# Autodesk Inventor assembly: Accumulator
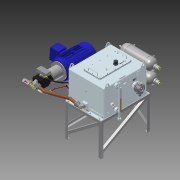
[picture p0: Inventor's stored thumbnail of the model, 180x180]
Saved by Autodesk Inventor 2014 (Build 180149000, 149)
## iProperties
Created: 2002-07
Part Number: Accumulator
Description: POWER PACK ASSY
Document SubType Name: Assembly
Designer: Autodesk, Inc.
Mass: 801000 g
Surface Area: 191391 cm^2
Volume: 112018 cm^3
Density: 7.15062 g/cm^3
Company: Autodesk, Inc.
_PSKETCH_MXID: 114
Control State: 0
Master: False
Checked Out: True
Shininess: 20.0
Length Units: 11272
Angle Units: 11279
Time Units: 11290
Mass Units: 11286
Length Display Precision: 3
Angle Display Precision: 2
Density: 0.0
Volumn: 0.0
Area: 0.0
PropertySet Name: Model Information
Title: Accumulator
Author: Autodesk, Inc.
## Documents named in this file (67)
- C:\Users\iTools\Desktop\tutorial files\Tube and Pipe\Accumulator\Accumulator.iam
- C:\Users\iTools\Desktop\tutorial files\Tube and Pipe\Accumulator\Parts\51361.ipt
- C:\Users\iTools\Desktop\tutorial files\Tube and Pipe\Accumulator\Parts\207905.ipt
- C:\Users\iTools\Desktop\tutorial files\Tube and Pipe\Accumulator\Parts\204389.ipt
- C:\Users\iTools\Desktop\tutorial files\Tube and Pipe\Accumulator\Parts\46959.ipt
- C:\Users\iTools\Desktop\tutorial files\Tube and Pipe\Accumulator\Parts\37454.ipt
- C:\Users\iTools\Desktop\tutorial files\Tube and Pipe\Accumulator\Parts\47290.ipt
- C:\Users\iTools\Desktop\tutorial files\Tube and Pipe\Accumulator\Parts\235517.ipt
- C:\Users\iTools\Desktop\tutorial files\Tube and Pipe\Accumulator\Parts\237648.ipt
- C:\Users\iTools\Desktop\tutorial files\Tube and Pipe\Accumulator\Parts\232894.ipt
- C:\Users\iTools\Desktop\tutorial files\Tube and Pipe\Accumulator\Parts\11587.ipt
- C:\Users\iTools\Desktop\tutorial files\Tube and Pipe\Accumulator\Parts\238807.ipt
- C:\Users\iTools\Desktop\tutorial files\Tube and Pipe\Accumulator\Parts\19754.ipt
- C:\Users\iTools\Desktop\tutorial files\Tube and Pipe\Accumulator\Parts\230976.ipt
- C:\Users\iTools\Desktop\tutorial files\Tube and Pipe\Accumulator\Parts\228458.ipt
- C:\Users\iTools\Desktop\tutorial files\Tube and Pipe\Accumulator\Parts\231851.ipt
- C:\Users\iTools\Desktop\tutorial files\Tube and Pipe\Accumulator\Parts\229672.ipt
- C:\Users\iTools\Desktop\tutorial files\Tube and Pipe\Accumulator\Parts\245671.ipt
- C:\Users\iTools\Desktop\tutorial files\Tube and Pipe\Accumulator\Parts\245667.ipt
- C:\Users\iTools\Desktop\tutorial files\Tube and Pipe\Accumulator\Parts\243992.ipt
- C:\Users\iTools\Desktop\tutorial files\Tube and Pipe\Accumulator\Parts\247502.ipt
- C:\Users\iTools\Desktop\tutorial files\Tube and Pipe\Accumulator\Parts\244752.ipt
- C:\Users\iTools\Desktop\tutorial files\Tube and Pipe\Accumulator\Parts\245748.ipt
- C:\Users\iTools\Desktop\tutorial files\Tube and Pipe\Accumulator\Parts\233841.ipt
- C:\Users\iTools\Desktop\tutorial files\Tube and Pipe\Accumulator\Parts\237738.ipt
- C:\Users\iTools\Desktop\tutorial files\Tube and Pipe\Accumulator\Parts\248216.ipt
- C:\Users\iTools\Desktop\tutorial files\Tube and Pipe\Accumulator\Parts\209140.ipt
- C:\Users\iTools\Desktop\tutorial files\Tube and Pipe\Accumulator\Parts\51573.ipt
- C:\Users\iTools\Desktop\tutorial files\Tube and Pipe\Accumulator\Parts\244403.ipt
- C:\Users\iTools\Desktop\tutorial files\Tube and Pipe\Accumulator\Parts\248780.ipt
- C:\Users\iTools\Desktop\tutorial files\Tube and Pipe\Accumulator\Parts\247846.ipt
- C:\Users\iTools\Desktop\tutorial files\Tube and Pipe\Accumulator\Parts\238527.ipt
- C:\Users\iTools\Desktop\tutorial files\Tube and Pipe\Accumulator\Parts\240811.ipt
- C:\Users\iTools\Desktop\tutorial files\Tube and Pipe\Accumulator\Parts\51442.iam
- C:\Users\iTools\Desktop\tutorial files\Tube and Pipe\Accumulator\Parts\248801.ipt
- C:\Users\iTools\Desktop\tutorial files\Tube and Pipe\Accumulator\Parts\46412.ipt
- C:\Users\iTools\Desktop\tutorial files\Tube and Pipe\Accumulator\Parts\HF32746.ipt
- C:\Users\iTools\Desktop\tutorial files\Tube and Pipe\Accumulator\Parts\R13811195.ipt
- C:\Users\iTools\Desktop\tutorial files\Tube and Pipe\Accumulator\Parts\220667.ipt
- C:\Users\iTools\Desktop\tutorial files\Tube and Pipe\Accumulator\Parts\557202.ipt
- C:\Users\iTools\Desktop\tutorial files\Tube and Pipe\Accumulator\Parts\558560.ipt
- C:\Users\iTools\Desktop\tutorial files\Tube and Pipe\Accumulator\Parts\248809.ipt
- C:\Users\iTools\Desktop\tutorial files\Tube and Pipe\Accumulator\Parts\237737n.ipt
- C:\Users\iTools\Desktop\tutorial files\Tube and Pipe\Accumulator\Parts\237739n.ipt
- C:\Users\iTools\Desktop\tutorial files\Tube and Pipe\Accumulator\Parts\HF33269.ipt
- C:\Users\iTools\Desktop\tutorial files\Tube and Pipe\Accumulator\Parts\HF32747.ipt
- C:\Users\iTools\Desktop\tutorial files\Tube and Pipe\Accumulator\AIP\piping runs.1067628895400.iam
- C:\Users\iTools\Desktop\tutorial files\Tube and Pipe\Accumulator\Parts\Mount Frame.iam
- C:\Users\iTools\Desktop\tutorial files\Tube and Pipe\Accumulator\Standard Parts\ANSI B18.2.1 - 5_8-11 UNC - 1.5(3).ipt
- C:\Users\iTools\Desktop\tutorial files\Tube and Pipe\Accumulator\Standard Parts\ANSI B18.2.1 - 3_8-16 UNC - 1(3).ipt
- C:\Users\iTools\Desktop\tutorial files\Tube and Pipe\Accumulator\Standard Parts\ANSI B18.2.1 - 5_8-11 UNC - 2.25(3).ipt
- C:\Users\iTools\Desktop\tutorial files\Tube and Pipe\Accumulator\Standard Parts\ANSI B18.2.1 - 1_2-13 UNC - 1(3).ipt
- C:\Users\iTools\Desktop\tutorial files\Tube and Pipe\Accumulator\Standard Parts\ANSI B18.2.1 - 1_2-13 UNC - 1.75(3).ipt
- C:\Users\iTools\Desktop\tutorial files\Tube and Pipe\Accumulator\Standard Parts\ANSI B18.2.1 - 3_8-16 UNC - 0.75(3).ipt
- C:\Program Files\Autodesk\Inventor 2010\Tutorial Files\Tube & Pipe\Accumulator\Parts\MC-B.ipt
- C:\Program Files\Autodesk\Inventor 2010\Tutorial Files\Tube & Pipe\Accumulator\Parts\MC-G.ipt
- C:\Program Files\Autodesk\Inventor 2010\Tutorial Files\Tube & Pipe\Accumulator\Parts\EL-BC9.ipt
- C:\Program Files\Autodesk\Inventor 2010\Tutorial Files\Tube & Pipe\Accumulator\Parts\C9C9G-C9GC9.ipt
- C:\Program Files\Autodesk\Inventor 2010\Tutorial Files\Tube & Pipe\Accumulator\Parts\EL-C9G.ipt
- C:\Program Files\Autodesk\Inventor 2010\Tutorial Files\Tube & Pipe\Accumulator\Parts\ST-A9G.ipt
- C:\Program Files\Autodesk\Inventor 2010\Tutorial Files\Tube & Pipe\Accumulator\Parts\STATO.ipt
- C:\Program Files\Autodesk\Inventor 2010\Tutorial Files\Tube & Pipe\Accumulator\Parts\Lock-nut.ipt
- C:\Program Files\Autodesk\Inventor 2010\Tutorial Files\Tube & Pipe\Accumulator\Parts\ST-BQ.ipt
- C:\Program Files\Autodesk\Inventor 2010\Tutorial Files\Tube & Pipe\Accumulator\Parts\ST-GG.ipt
- C:\Program Files\Autodesk\Inventor 2010\Tutorial Files\Tube & Pipe\Accumulator\Parts\C9C9C9_C9C9A9_C9A9C9.ipt
- C:\Program Files\Autodesk\Inventor 2010\Tutorial Files\Tube & Pipe\Accumulator\Parts\ST-BC9.ipt
- C:\Program Files\Autodesk\Inventor 2010\Tutorial Files\Tube & Pipe\Accumulator\Parts\Threaded Weld Stud.ipt
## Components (138 placed, 53 different names)
1. Tube & Pipe Runs [sub-assembly]
2. 51361:1 — Mate:1, Mate:2, Mate:3, Mate:4, Mate:5, Mate:6, Mate:7, Mate:8, Mate:9, Mate:10, Mate:11, Mate:12, Mate:21, Mate:22, Mate:23, Mate:25, Mate:30, Mate:33, Mate:40, Mate:41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
3. 51442:1 [sub-assembly] — Mate:55, Mate:56, Angle:3, Mate:105, Mate:106, Angle:5, Mate:172, Mate:173
4. 244752:2 — Mate:120, Flush:3, Angle:6, Mate:121, Mate:122, Mate:158
5. 244752:1 — Mate:118, Mate:119, Flush:3, Angle:7, Mate:123, Mate:124, Mate:159
6. 207905:1 — Mate:1, Mate:7, Mate:8, Mate:14, Mate:18, Mate:120
7. 207905:2 — Mate:2, Mate:5, Mate:6, Mate:13, Mate:17, Mate:63, Mate:64, Mate:118, Mate:119
8. 207905:3 — Mate:4, Mate:11, Mate:12, Mate:15, Mate:19
9. 207905:4 — Mate:3, Mate:9, Mate:10, Mate:16, Mate:20
10. 46959:1 — Mate:13, Mate:17
11. 46959:2 — Mate:14, Mate:18
12. 46959:3 — Mate:16, Mate:20
13. 46959:4 — Mate:15, Mate:19
14. 47290:1 — Mate:24, Mate:25, Mate:26, Mate:27, Mate:28, Mate:29, Mate:38, Mate:39, Mate:59, Mate:60, Mate:97, Mate:98, Mate:99
15. 37454:1 — Mate:21, Mate:22, Mate:23, Mate:24, Mate:26
16. 235517:1 — Mate:27, Mate:28, Mate:29
17. 237648:1 — Mate:30, Mate:115, Mate:116, Mate:125, Mate:126, Mate:128, Mate:129
18. 11587:1 — Mate:31, Mate:32, Mate:33, Mate:94, Mate:95
19. 245671:1 — Mate:42, Mate:43, Mate:44, Mate:45
20. 245667:1 — Mate:44, Mate:45, Angle:1
21. 243992:1 — Mate:57, Mate:58, Mate:107
22. 248801:1 — Mate:52, Mate:53, Mate:54
23. 245748:1 — Mate:48, Mate:51, Mate:52
24. 245748:2 — Mate:49, Mate:50
25. 230976:1 — Mate:38, Mate:39
26. 229672:1 — Mate:40, Mate:41
27. 238807:1 — Mate:46, Mate:47, Angle:2, Mate:164, Mate:165
28. 248809:1 — Mate:105, Mate:106, Angle:5, Mate:107, Mate:108, Mate:113, Mate:114, Angle:8
29. 237738:1 — Mate:55, Mate:56, Angle:3, Flush:6, Mate:163
30. 248780:1 — Mate:57, Mate:58, Mate:108
31. 209140:2 — Mate:123, Mate:124, Mate:156
32. 209140:3 — Mate:121, Mate:122, Mate:157
33. 220667:1 — Mate:94, Mate:95, Mate:96
34. 557202:1 — Mate:97, Mate:98, Mate:99
35. 558560:1 — Mate:100, Mate:101, Mate:102
36. 248780:2 — Mate:113, Mate:114, Mate:134, Mate:135
37. 19754:1 — Mate:115, Mate:116
38. 233841:1 — Mate:128, Mate:129
39. 237737n:1
40. 248216:1 — Mate:138, Mate:139, Angle:9, Mate:140, Mate:141
41. 51573:1 — Mate:134, Mate:135, Angle:8, Mate:136, Mate:137, Angle:9
42. 244403:1 — Mate:136, Mate:137, Mate:138, Mate:139
43. 247846:1 — Mate:140, Mate:141
44. 237739n:1 — Mate:166, Mate:167
45. 238527:1 — Mate:146, Mate:147, Angle:10, Mate:161, Mate:162
46. 247502:1 — Mate:144, Mate:145, Mate:146, Mate:147
47. 240811:1 — Mate:156, Mate:159
48. 240811:2 — Mate:157, Mate:158
49. 46412:1 — Mate:160
50. HF32746:1 — Flush:6, Mate:163
51. HF32746:2 — Mate:161, Mate:162
52. HF32746:3 — Mate:164, Mate:165
53. HF32746:4 — Mate:166, Mate:167
54. HF33269:1 — Flush:7, Mate:168, Mate:169, Mate:170, Mate:171
55. HF32747:1 — Mate:170, Mate:171
56. HF33269:2 — Mate:172, Mate:173, Mate:174, Mate:175, Mate:176
57. HF32747:2 — Mate:175, Mate:176
58. Mount Frame:1 [sub-assembly] — Flush:8, Flush:9
59. 232894:1 — Mate:31, Mate:32
60. 232894:2
61. 232894:3
62. 232894:4
63. Hex Cap Screw - Inch 3/8-16 UNC - 0.75:1
64. 204389:1 — Mate:59, Mate:60
65. Hex Cap Screw - Inch 3/8-16 UNC - 0.75:2
66. 204389:2
67. Hex Cap Screw - Inch 3/8-16 UNC - 0.75:3
68. 204389:3
69. Hex Cap Screw - Inch 3/8-16 UNC - 0.75:4
70. 204389:4
71. Hex Cap Screw - Inch 3/8-16 UNC - 0.75:5
72. 204389:6
73. Hex Cap Screw - Inch 3/8-16 UNC - 0.75:6
74. 204389:7
75. Hex Cap Screw - Inch 3/8-16 UNC - 0.75:7
76. 204389:9
77. Hex Cap Screw - Inch 3/8-16 UNC - 0.75:8
78. 204389:10
79. Hex Cap Screw - Inch 3/8-16 UNC - 0.75:9
80. 204389:12
81. Hex Cap Screw - Inch 3/8-16 UNC - 0.75:10
82. 204389:13
83. Hex Cap Screw - Inch 3/8-16 UNC - 0.75:11
84. 204389:14
85. Hex Cap Screw - Inch 3/8-16 UNC - 0.75:12
86. 204389:15
87. Hex Cap Screw - Inch 3/8-16 UNC - 1:1
88. 231851:1 — Mate:64, Mate:66
89. Hex Cap Screw - Inch 3/8-16 UNC - 1:5
90. 231851:2 — Mate:63, Mate:65
91. Hex Cap Screw - Inch 3/8-16 UNC - 1:2
92. 231851:3
93. Hex Cap Screw - Inch 3/8-16 UNC - 1:6
94. 231851:4
95. Hex Cap Screw - Inch 3/8-16 UNC - 1:3
96. 231851:5
97. Hex Cap Screw - Inch 3/8-16 UNC - 1:7
98. 231851:6
99. Hex Cap Screw - Inch 3/8-16 UNC - 1:4
100. 231851:7
101. Hex Cap Screw - Inch 3/8-16 UNC - 1:8
102. 231851:8
103. Hex Cap Screw - Inch 1/2-13 UNC - 1.75:1
104. Hex Cap Screw - Inch 1/2-13 UNC - 1.75:2
105. Hex Cap Screw - Inch 1/2-13 UNC - 1.75:3
106. Hex Cap Screw - Inch 1/2-13 UNC - 1.75:4
107. Hex Cap Screw - Inch 1/2-13 UNC - 1:1
108. Hex Cap Screw - Inch 1/2-13 UNC - 1:3
109. Hex Cap Screw - Inch 1/2-13 UNC - 1:5
110. Hex Cap Screw - Inch 1/2-13 UNC - 1:7
111. Hex Cap Screw - Inch 1/2-13 UNC - 1:2
112. Hex Cap Screw - Inch 1/2-13 UNC - 1:4
113. Hex Cap Screw - Inch 1/2-13 UNC - 1:6
114. Hex Cap Screw - Inch 1/2-13 UNC - 1:8
115. Hex Cap Screw - Inch 5/8-11 UNC - 1.5:1
116. 228458:1 — Mate:85
117. Hex Cap Screw - Inch 5/8-11 UNC - 1.5:5
118. 228458:5 — Mate:89
119. Hex Cap Screw - Inch 5/8-11 UNC - 1.5:2
120. 228458:2
121. Hex Cap Screw - Inch 5/8-11 UNC - 1.5:6
122. 228458:6
123. Hex Cap Screw - Inch 5/8-11 UNC - 1.5:3
124. 228458:3
125. Hex Cap Screw - Inch 5/8-11 UNC - 1.5:7
126. 228458:7
127. Hex Cap Screw - Inch 5/8-11 UNC - 1.5:4
128. 228458:4
129. Hex Cap Screw - Inch 5/8-11 UNC - 1.5:8
130. 228458:8
131. R13811195:9
132. Hex Cap Screw - Inch 5/8-11 UNC - 2.25:1
133. R13811195:16
134. Hex Cap Screw - Inch 5/8-11 UNC - 2.25:2
135. R13811195:17
136. Hex Cap Screw - Inch 5/8-11 UNC - 2.25:3
137. R13811195:18
138. Hex Cap Screw - Inch 5/8-11 UNC - 2.25:4
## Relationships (137: Mate 123, Angle 9, Flush 5)
- Mate:1: 51361:1 ↔ 207905:1
- Mate:2: 51361:1 ↔ 207905:2
- Mate:3: 51361:1 ↔ 207905:4
- Mate:4: 51361:1 ↔ 207905:3
- Mate:5: 51361:1 ↔ 207905:2
- Mate:6: 51361:1 ↔ 207905:2
- Mate:7: 51361:1 ↔ 207905:1
- Mate:8: 51361:1 ↔ 207905:1
- Mate:9: 51361:1 ↔ 207905:4
- Mate:10: 51361:1 ↔ 207905:4
- Mate:11: 51361:1 ↔ 207905:3
- Mate:12: 51361:1 ↔ 207905:3
- Mate:13: 207905:2 ↔ 46959:1
- Mate:14: 207905:1 ↔ 46959:2
- Mate:15: 207905:3 ↔ 46959:4
- Mate:16: 207905:4 ↔ 46959:3
- Mate:17: 207905:2 ↔ 46959:1
- Mate:18: 207905:1 ↔ 46959:2
- Mate:19: 207905:3 ↔ 46959:4
- Mate:20: 207905:4 ↔ 46959:3
- Mate:21: 51361:1 ↔ 37454:1
- Mate:22: 51361:1 ↔ 37454:1
- Mate:23: 51361:1 ↔ 37454:1
- Mate:24: 47290:1 ↔ 37454:1
- Mate:25: 51361:1 ↔ 47290:1
- Mate:26: 47290:1 ↔ 37454:1
- Mate:27: 47290:1 ↔ 235517:1
- Mate:28: 47290:1 ↔ 235517:1
- Mate:29: 47290:1 ↔ 235517:1
- Mate:30: 51361:1 ↔ 237648:1
- Mate:31: 11587:1 ↔ 232894:1
- Mate:32: 11587:1 ↔ 232894:1
- Mate:33: 51361:1 ↔ 11587:1
- Mate:38: 47290:1 ↔ 230976:1
- Mate:39: 47290:1 ↔ 230976:1
- Mate:40: 51361:1 ↔ 229672:1
- Mate:41: 51361:1 ↔ 229672:1
- Mate:42: 51361:1 ↔ 245671:1
- Mate:43: 51361:1 ↔ 245671:1
- Mate:44: 245671:1 ↔ 245667:1
- Mate:45: 245671:1 ↔ 245667:1
- Angle:1: 51361:1 ↔ 245667:1
- Mate:46: 51361:1 ↔ 238807:1
- Mate:47: 51361:1 ↔ 238807:1
- Angle:2: 51361:1 ↔ 238807:1
- Mate:48: 51361:1 ↔ 245748:1
- Mate:49: 51361:1 ↔ 245748:2
- Mate:50: 51361:1 ↔ 245748:2
- Mate:51: 51361:1 ↔ 245748:1
- Mate:52: 248801:1 ↔ 245748:1
- Mate:53: 51361:1 ↔ 248801:1
- Mate:54: 51361:1 ↔ 248801:1
- Mate:55: 51442:1 ↔ 237738:1
- Mate:56: 51442:1 ↔ 237738:1
- Angle:3: 51442:1 ↔ 237738:1
- Mate:57: 243992:1 ↔ 248780:1
- Mate:58: 243992:1 ↔ 248780:1
- Mate:59: 47290:1 ↔ 204389:1
- Mate:60: 47290:1 ↔ 204389:1
- Mate:63: 207905:2 ↔ 231851:2
- Mate:64: 207905:2 ↔ 231851:1
- Mate:65: 51361:1 ↔ 231851:2
- Mate:66: 51361:1 ↔ 231851:1
- Mate:85: 51361:1 ↔ 228458:1
- Mate:89: 51361:1 ↔ 228458:5
- Mate:94: 11587:1 ↔ 220667:1
- Mate:95: 11587:1 ↔ 220667:1
- Mate:96: 51361:1 ↔ 220667:1
- Mate:97: 47290:1 ↔ 557202:1
- Mate:98: 47290:1 ↔ 557202:1
- Mate:99: 47290:1 ↔ 557202:1
- Mate:100: 51361:1 ↔ 558560:1
- Mate:101: 51361:1 ↔ 558560:1
- Mate:102: 51361:1 ↔ 558560:1
- Mate:105: 51442:1 ↔ 248809:1
- Mate:106: 51442:1 ↔ 248809:1
- Angle:5: 51442:1 ↔ 248809:1
- Mate:107: 243992:1 ↔ 248809:1
- Mate:108: 248809:1 ↔ 248780:1
- Mate:113: 248809:1 ↔ 248780:2
- Mate:114: 248809:1 ↔ 248780:2
- Mate:115: 237648:1 ↔ 19754:1
- Mate:116: 237648:1 ↔ 19754:1
- Mate:118: 244752:1 ↔ 207905:2
- Mate:119: 244752:1 ↔ 207905:2
- Mate:120: 244752:2 ↔ 207905:1
- Flush:3: 244752:2 ↔ 244752:1
- Angle:6: 51361:1 ↔ 244752:2
- Angle:7: 51361:1 ↔ 244752:1
- Mate:121: 244752:2 ↔ 209140:3
- Mate:122: 244752:2 ↔ 209140:3
- Mate:123: 244752:1 ↔ 209140:2
- Mate:124: 244752:1 ↔ 209140:2
- Mate:125: 51361:1 ↔ 237648:1
- Mate:126: 51361:1 ↔ 237648:1
- Mate:128: 237648:1 ↔ 233841:1
- Mate:129: 237648:1 ↔ 233841:1
- Mate:134: 248780:2 ↔ 51573:1
- Mate:135: 248780:2 ↔ 51573:1
- Angle:8: 248809:1 ↔ 51573:1
- Mate:136: 51573:1 ↔ 244403:1
- Mate:137: 51573:1 ↔ 244403:1
- Mate:138: 248216:1 ↔ 244403:1
- Mate:139: 248216:1 ↔ 244403:1
- Angle:9: 248216:1 ↔ 51573:1
- Mate:140: 248216:1 ↔ 247846:1
- Mate:141: 248216:1 ↔ 247846:1
- Mate:144: 51361:1 ↔ 247502:1
- Mate:145: 51361:1 ↔ 247502:1
- Mate:146: 238527:1 ↔ 247502:1
- Mate:147: 238527:1 ↔ 247502:1
- Angle:10: 51361:1 ↔ 238527:1
- Mate:156: 209140:2 ↔ 240811:1
- Mate:157: 209140:3 ↔ 240811:2
- Mate:158: 244752:2 ↔ 240811:2
- Mate:159: 244752:1 ↔ 240811:1
- Mate:160: 51361:1 ↔ 46412:1
- Flush:6: 237738:1 ↔ HF32746:1
- Mate:161: 238527:1 ↔ HF32746:2
- Mate:162: 238527:1 ↔ HF32746:2
- Mate:163: 237738:1 ↔ HF32746:1
- Mate:164: 238807:1 ↔ HF32746:3
- Mate:165: 238807:1 ↔ HF32746:3
- Mate:166: 237739n:1 ↔ HF32746:4
- Mate:167: 237739n:1 ↔ HF32746:4
- Flush:7: 51361:1 ↔ HF33269:1
- Mate:168: 51361:1 ↔ HF33269:1
- Mate:169: HF33269:1
- Mate:170: HF33269:1 ↔ HF32747:1
- Mate:171: HF33269:1 ↔ HF32747:1
- Mate:172: 51442:1 ↔ HF33269:2
- Mate:173: 51442:1 ↔ HF33269:2
- Mate:174: HF33269:2
- Mate:175: HF33269:2 ↔ HF32747:2
- Mate:176: HF33269:2 ↔ HF32747:2
- Flush:8: 51361:1 ↔ Mount Frame:1
- Flush:9: 51361:1 ↔ Mount Frame:1
